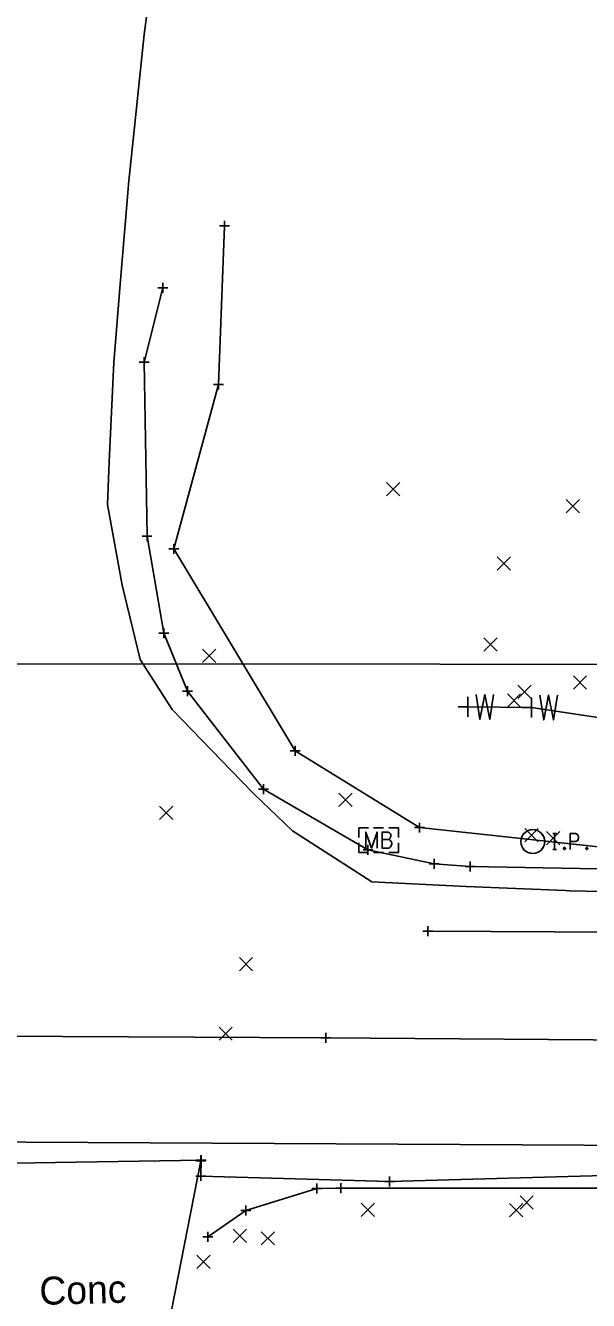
# Model space of a CAD drawing. Extents: x 146022 to 147632, y 437624 to 440659.
# Drawn here: x 146801.3 to 146857.8, y 438601.8 to 438729.9 of the extents above; entities that cross this region are included whole.
import ezdxf

# ---------------------------------------------------------------- set-up
doc = ezdxf.new("R2010")
doc.units = 0
for name, color, linetype in [('_CIVIL_CONSTRUCTION', 7, 'Continuous'), ('DR_Channel', 7, 'Continuous'), ('DR_P_Paved_Gutter', 7, 'Continuous'), ('DR_X_Text', 7, 'Continuous'), ('DT_X_Spot_Elev', 7, 'Continuous'), ('GE_P_Alignment_100_Distances', 7, 'Continuous'), ('PF_X_Ground_Line', 7, 'Continuous'), ('PV_P_Curb', 7, 'Continuous'), ('PV_P_Shoulder', 7, 'Continuous'), ('RD_P_Anchor_Assembly', 7, 'Continuous'), ('RD_P_GR_Lt_Replaced', 7, 'Continuous'), ('RD_P_GR_Rt', 7, 'Continuous'), ('SC_Scratch1', 7, 'Continuous'), ('SC_Scratch3', 7, 'Continuous'), ('UT_X_Water', 7, 'Continuous')]:
    doc.layers.add(name, color=color, linetype=linetype)

msp = doc.modelspace()

# ---------------------------------------------------------------- linework, layer by layer
at = {"layer": '_CIVIL_CONSTRUCTION'}
for p, q in [((146837.54, 438682.66), (146838.88, 438684)), ((146837.54, 438684), (146838.88, 438682.66)), ((146855.57, 438680.97), (146856.91, 438682.31)), ((146855.57, 438682.31), (146856.91, 438680.97)), ((146848.65, 438675.2), (146849.98, 438676.53)), ((146848.65, 438676.53), (146849.98, 438675.2)), ((146847.32, 438667.06), (146848.66, 438668.4)), ((146847.32, 438668.4), (146848.66, 438667.06)), ((146819.04, 438665.91), (146820.37, 438667.25)), ((146819.04, 438667.25), (146820.37, 438665.91)), ((146856.3, 438663.24), (146857.63, 438664.58)), ((146856.3, 438664.58), (146857.63, 438663.24)), ((146850.73, 438662.32), (146852.07, 438663.66)), ((146850.73, 438663.66), (146852.07, 438662.32)), ((146849.67, 438661.45), (146851, 438662.79)), ((146849.67, 438662.79), (146851, 438661.45)), ((146832.75, 438651.47), (146834.08, 438652.8)), ((146832.75, 438652.8), (146834.08, 438651.47)), ((146814.71, 438650.16), (146816.05, 438651.5)), ((146814.71, 438651.5), (146816.05, 438650.16)), ((146851.42, 438647.92), (146852.75, 438649.25)), ((146851.42, 438649.25), (146852.75, 438647.92)), ((146853.6, 438647.62), (146854.93, 438648.95)), ((146853.6, 438648.95), (146854.93, 438647.62)), ((146822.75, 438634.95), (146824.08, 438636.28)), ((146822.75, 438636.28), (146824.08, 438634.95)), ((146820.71, 438627.97), (146822.04, 438629.3)), ((146820.71, 438629.3), (146822.04, 438627.97)), ((146850.95, 438610.99), (146852.28, 438612.33)), ((146850.95, 438612.33), (146852.28, 438610.99)), ((146834.99, 438610.26), (146836.32, 438611.59)), ((146834.99, 438611.59), (146836.32, 438610.26)), ((146849.89, 438610.23), (146851.23, 438611.57)), ((146849.89, 438611.57), (146851.23, 438610.23)), ((146822.12, 438607.66), (146823.45, 438609)), ((146822.12, 438609), (146823.45, 438607.66)), ((146824.95, 438607.4), (146826.28, 438608.73)), ((146824.95, 438608.73), (146826.28, 438607.4)), ((146818.48, 438605.03), (146819.81, 438606.36)), ((146818.48, 438606.36), (146819.81, 438605.03))]:
    msp.add_line(p, q, dxfattribs=at)
at = {"layer": 'DR_Channel'}
msp.add_lwpolyline([(146815.07, 438703.58), (146813.17, 438696.09), (146813.47, 438678.63), (146815.15, 438668.88), (146817.53, 438663.05), (146825.17, 438653.2), (146835.67, 438647.11), (146842.31, 438645.69), (146845.94, 438645.44), (146866.12, 438645.06), (146880.69, 438644.85), (146884.43, 438645)], dxfattribs=at)
at = {"layer": 'DR_P_Paved_Gutter'}
msp.add_lwpolyline([(146819.58, 438608.21), (146823.41, 438610.85), (146830.52, 438613.07), (146832.93, 438613.11), (146860.49, 438613.12), (146880.55, 438612.95), (146884.06, 438612.71)], dxfattribs=at)
at = {"layer": 'DT_X_Spot_Elev'}
for p, q in [((146836.24, 438649.3), (146837.24, 438649.3)), ((146836.75, 438648.08), (146836.75, 438648.08)), ((146836.24, 438646.85), (146837.24, 438646.85))]:
    msp.add_line(p, q, dxfattribs=at)
for points in [[(146834.75, 438648.33), (146834.75, 438649.3), (146835.72, 438649.3)], [(146837.76, 438649.3), (146838.75, 438649.3), (146838.75, 438648.33)], [(146835.72, 438646.85), (146834.75, 438646.85), (146834.75, 438647.82)], [(146835.45, 438647.28), (146835.45, 438648.88), (146836.03, 438647.28), (146836.59, 438648.88), (146836.59, 438647.28)], [(146837.77, 438648.15), (146837.83, 438648.21), (146837.87, 438648.25), (146837.9, 438648.28), (146837.91, 438648.31), (146837.94, 438648.36), (146837.95, 438648.4), (146837.97, 438648.49), (146837.97, 438648.52), (146837.97, 438648.57), (146837.96, 438648.65), (146837.94, 438648.71), (146837.9, 438648.76), (146837.83, 438648.81), (146837.78, 438648.84), (146837.76, 438648.85), (146837.7, 438648.88), (146837.08, 438648.88), (146837.08, 438647.28), (146837.77, 438647.28), (146837.86, 438647.33), (146837.94, 438647.39), (146838, 438647.49), (146838.04, 438647.6), (146838.05, 438647.72), (146838.05, 438647.79), (146838.02, 438647.87), (146837.97, 438647.98), (146837.91, 438648.06), (146837.77, 438648.15), (146837.08, 438648.15)], [(146838.75, 438647.82), (146838.75, 438646.85), (146837.76, 438646.85)]]:
    msp.add_lwpolyline(points, dxfattribs=at)
at = {"layer": 'GE_P_Alignment_100_Distances'}
msp.add_lwpolyline([(146750.22, 438665.83), (146889.21, 438665.72), (146992.98, 438665.29), (147118.65, 438665.14)], dxfattribs=at)
at = {"layer": 'PF_X_Ground_Line'}
msp.add_lwpolyline([(146879.48, 438644.78), (146862.52, 438646.99), (146840.85, 438649.33), (146828.35, 438657.05), (146816.17, 438677.33), (146820.64, 438693.86), (146821.24, 438709.8)], dxfattribs=at)
at = {"layer": 'PV_P_Curb'}
msp.add_line((146760.89, 438628.57), (146831.42, 438628.2), dxfattribs=at)
msp.add_lwpolyline([(146885.16, 438627.81), (146831.42, 438628.2)], dxfattribs=at)
at = {"layer": 'PV_P_Shoulder'}
for points in [[(146854.24, 438648.73), (146854.59, 438648.73)], [(146854.25, 438648.74), (146854.6, 438648.74)], [(146854.42, 438647.14), (146854.42, 438648.74)], [(146854.42, 438647.13), (146854.42, 438648.73)], [(146855.98, 438647.13), (146855.98, 438648.73), (146856.51, 438648.73), (146856.57, 438648.72), (146856.64, 438648.69), (146856.68, 438648.67), (146856.71, 438648.64), (146856.75, 438648.58), (146856.79, 438648.52), (146856.81, 438648.42), (146856.81, 438648.26), (146856.8, 438648.21), (146856.78, 438648.14), (146856.73, 438648.05), (146856.69, 438648.01), (146856.66, 438647.99), (146856.6, 438647.96), (146856.51, 438647.95), (146855.98, 438647.95)], [(146855.99, 438647.14), (146855.99, 438648.74), (146856.52, 438648.74), (146856.57, 438648.72), (146856.65, 438648.7), (146856.68, 438648.67), (146856.71, 438648.65), (146856.76, 438648.58), (146856.79, 438648.52), (146856.81, 438648.42), (146856.81, 438648.27), (146856.8, 438648.22), (146856.78, 438648.14), (146856.74, 438648.05), (146856.69, 438648.02), (146856.66, 438647.99), (146856.6, 438647.97), (146856.52, 438647.95), (146855.99, 438647.95)], [(146854.24, 438647.13), (146854.59, 438647.13)], [(146854.25, 438647.14), (146854.6, 438647.14)], [(146855.38, 438647.35), (146855.44, 438647.35), (146855.47, 438647.32), (146855.5, 438647.27), (146855.5, 438647.21), (146855.47, 438647.16), (146855.44, 438647.14), (146855.38, 438647.14), (146855.35, 438647.16), (146855.31, 438647.21), (146855.31, 438647.27), (146855.35, 438647.32), (146855.38, 438647.35)], [(146855.38, 438647.34), (146855.43, 438647.34), (146855.47, 438647.32), (146855.5, 438647.27), (146855.5, 438647.21), (146855.47, 438647.16), (146855.43, 438647.13), (146855.38, 438647.13), (146855.34, 438647.16), (146855.31, 438647.21), (146855.31, 438647.27), (146855.34, 438647.32), (146855.38, 438647.34)], [(146857.63, 438647.35), (146857.68, 438647.35), (146857.72, 438647.32), (146857.75, 438647.27), (146857.75, 438647.21), (146857.72, 438647.16), (146857.68, 438647.14), (146857.63, 438647.14), (146857.6, 438647.16), (146857.56, 438647.21), (146857.56, 438647.27), (146857.6, 438647.32), (146857.63, 438647.35)], [(146857.63, 438647.34), (146857.68, 438647.34), (146857.71, 438647.32), (146857.75, 438647.27), (146857.75, 438647.21), (146857.71, 438647.16), (146857.68, 438647.13), (146857.63, 438647.13), (146857.59, 438647.16), (146857.56, 438647.21), (146857.56, 438647.27), (146857.59, 438647.32), (146857.63, 438647.34)]]:
    msp.add_lwpolyline(points, dxfattribs=at)
for centre in [(146852.22, 438647.93), (146852.23, 438647.93)]:
    msp.add_circle(centre, 1.2, dxfattribs=at)
at = {"layer": 'RD_P_Anchor_Assembly'}
for p, q in [((146820.74, 438709.8), (146821.74, 438709.8)), ((146821.24, 438710.3), (146821.24, 438709.3)), ((146821.24, 438709.8), (146821.24, 438709.8)), ((146814.57, 438703.58), (146815.57, 438703.58)), ((146815.07, 438704.08), (146815.07, 438703.08)), ((146815.07, 438703.58), (146815.07, 438703.58)), ((146813.17, 438696.59), (146813.17, 438695.59)), ((146812.67, 438696.09), (146813.67, 438696.09)), ((146813.17, 438696.09), (146813.17, 438696.09)), ((146820.64, 438694.36), (146820.64, 438693.36)), ((146820.14, 438693.86), (146821.14, 438693.86)), ((146820.64, 438693.86), (146820.64, 438693.86)), ((146812.97, 438678.63), (146813.97, 438678.63)), ((146813.47, 438679.13), (146813.47, 438678.13)), ((146813.47, 438678.63), (146813.47, 438678.63)), ((146815.67, 438677.33), (146816.67, 438677.33)), ((146816.17, 438677.83), (146816.17, 438676.83)), ((146816.17, 438677.33), (146816.17, 438677.33)), ((146814.65, 438668.88), (146815.65, 438668.88)), ((146815.15, 438669.38), (146815.15, 438668.38)), ((146815.15, 438668.88), (146815.15, 438668.88)), ((146817.53, 438663.55), (146817.53, 438662.55)), ((146817.03, 438663.05), (146818.03, 438663.05)), ((146817.53, 438663.05), (146817.53, 438663.05)), ((146827.85, 438657.05), (146828.85, 438657.05)), ((146828.35, 438657.55), (146828.35, 438656.55)), ((146828.35, 438657.05), (146828.35, 438657.05)), ((146824.67, 438653.2), (146825.67, 438653.2)), ((146825.17, 438653.7), (146825.17, 438652.7)), ((146825.17, 438653.2), (146825.17, 438653.2)), ((146840.35, 438649.33), (146841.35, 438649.33)), ((146840.85, 438649.83), (146840.85, 438648.83)), ((146840.85, 438649.33), (146840.85, 438649.33)), ((146835.17, 438647.11), (146836.17, 438647.11)), ((146835.67, 438647.61), (146835.67, 438646.61)), ((146835.67, 438647.11), (146835.67, 438647.11)), ((146841.81, 438645.69), (146842.81, 438645.69)), ((146842.31, 438646.19), (146842.31, 438645.19)), ((146842.31, 438645.69), (146842.31, 438645.69)), ((146845.44, 438645.44), (146846.44, 438645.44)), ((146845.94, 438645.94), (146845.94, 438644.94)), ((146845.94, 438645.44), (146845.94, 438645.44)), ((146841.19, 438638.94), (146842.19, 438638.94)), ((146841.69, 438639.44), (146841.69, 438638.44)), ((146841.69, 438638.94), (146841.69, 438638.94)), ((146831.42, 438628.7), (146831.42, 438627.7)), ((146830.92, 438628.2), (146831.92, 438628.2)), ((146831.42, 438628.2), (146831.42, 438628.2)), ((146818.36, 438615.87), (146819.36, 438615.87)), ((146818.42, 438615.92), (146819.42, 438615.92)), ((146818.86, 438616.37), (146818.86, 438615.37)), ((146818.86, 438615.87), (146818.86, 438615.87)), ((146818.92, 438616.42), (146818.92, 438615.42)), ((146818.92, 438615.92), (146818.92, 438615.92)), ((146818.89, 438614.83), (146818.89, 438613.83)), ((146818.39, 438614.33), (146819.39, 438614.33)), ((146818.89, 438614.33), (146818.89, 438614.33)), ((146830.52, 438613.57), (146830.52, 438612.57)), ((146832.93, 438613.61), (146832.93, 438612.61)), ((146837.32, 438613.79), (146838.32, 438613.79)), ((146837.82, 438614.29), (146837.82, 438613.29)), ((146837.82, 438613.79), (146837.82, 438613.79)), ((146830.02, 438613.07), (146831.02, 438613.07)), ((146830.52, 438613.07), (146830.52, 438613.07)), ((146832.43, 438613.11), (146833.43, 438613.11)), ((146832.93, 438613.11), (146832.93, 438613.11)), ((146822.91, 438610.85), (146823.91, 438610.85)), ((146823.41, 438611.35), (146823.41, 438610.35)), ((146823.41, 438610.85), (146823.41, 438610.85)), ((146819.08, 438608.21), (146820.08, 438608.21)), ((146819.58, 438608.71), (146819.58, 438607.71)), ((146819.58, 438608.21), (146819.58, 438608.21))]:
    msp.add_line(p, q, dxfattribs=at)
at = {"layer": 'RD_P_GR_Lt_Replaced'}
for points in [[(146816.74, 438756.13), (146815.49, 438746.21), (146815.33, 438744.99), (146814, 438735.08), (146813.18, 438729.02), (146812.13, 438719.07), (146811.63, 438714.31), (146810.82, 438704.35), (146810.14, 438696.07), (146809.68, 438686.08), (146809.49, 438681.81), (146810.98, 438673.68), (146812.77, 438666.23), (146816.01, 438661.2), (146822.96, 438654.01), (146824.25, 438652.68), (146828.1, 438649), (146836.07, 438643.9), (146845.52, 438643.41), (146855.51, 438643.01), (146855.93, 438642.99), (146865.65, 438642.79), (146875.65, 438642.66), (146884.35, 438642.84)], [(146880.85, 438613.68), (146860.56, 438614.41), (146837.82, 438613.79), (146818.89, 438614.33), (146818.92, 438615.92), (146795.87, 438615.54), (146788.31, 438613.93), (146720.31, 438615.03), (146712.35, 438615.26)]]:
    msp.add_lwpolyline(points, dxfattribs=at)
at = {"layer": 'RD_P_GR_Rt'}
for p, q in [((146845.7, 438660.46), (146845.7, 438662.46)), ((146852.1, 438660.4), (146852.1, 438662.4)), ((146845.7, 438661.46), (146844.74, 438661.46)), ((146852.1, 438661.4), (146851.15, 438661.4))]:
    msp.add_line(p, q, dxfattribs=at)
for points in [[(146846.54, 438662.71), (146846.91, 438660.21), (146847.41, 438662.71), (146847.9, 438660.21), (146848.29, 438662.71)], [(146852.94, 438662.65), (146853.32, 438660.15), (146853.81, 438662.65), (146854.3, 438660.15), (146854.7, 438662.65)]]:
    msp.add_lwpolyline(points, dxfattribs=at)
at = {"layer": 'SC_Scratch1'}
msp.add_lwpolyline([(146815.95, 438585.38), (146815.9, 438600.66), (146818.86, 438615.87)], dxfattribs=at)
at = {"layer": 'SC_Scratch3'}
msp.add_line((146841.69, 438638.94), (146885, 438638.71), dxfattribs=at)
msp.add_lwpolyline([(146543.08, 438618.44), (146597.03, 438618.35), (146664.15, 438618.22), (146719.64, 438618.19), (146788.82, 438617.8), (146882.32, 438617.3)], dxfattribs=at)
at = {"layer": 'UT_X_Water'}
msp.add_lwpolyline([(146845.7, 438661.46), (146852.1, 438661.4), (146858.98, 438660.35), (146861.8, 438659.52), (146863.77, 438659.3), (146865.3, 438656.94), (146867.7, 438657.05), (146867.76, 438657.02), (146867.85, 438659.5), (146871.96, 438659.5), (146879.02, 438658.4), (146886.6, 438657.02)], dxfattribs=at)

# ---------------------------------------------------------------- texts
at = {"layer": 'DR_X_Text'}
msp.add_text('Conc', height=2.8, rotation=1.4771, dxfattribs=at).set_placement((146802.69, 438601.38))

doc.saveas('drawing.dxf')
